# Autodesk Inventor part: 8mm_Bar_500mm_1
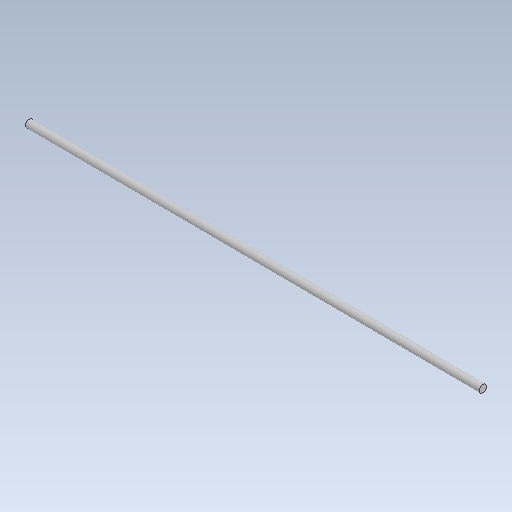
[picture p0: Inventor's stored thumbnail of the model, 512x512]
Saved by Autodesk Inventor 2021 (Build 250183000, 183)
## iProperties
Created: 2026-10
Part Number: 8mm_Bar_500mm_1
Material: Steel
Document SubType Name: Modeling
Designer: hp
Density: 7.85 g/cm^3
Appearance: Default
Author: hp
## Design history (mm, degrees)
feature "Body1"
body "Solid1"
